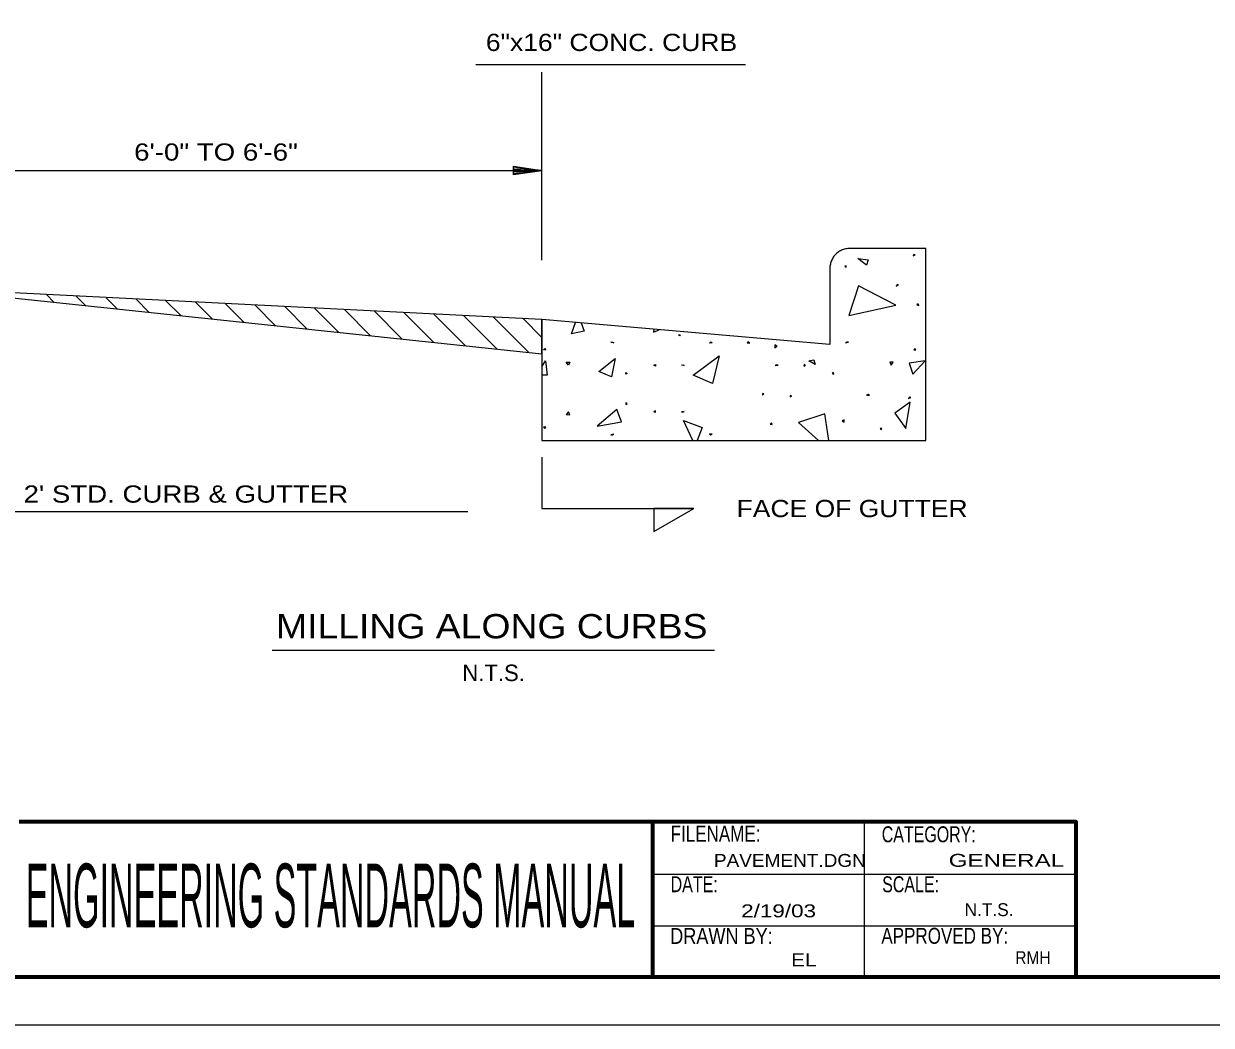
# Model space of a CAD drawing. Extents: x 44.6 to 61.6, y -38.7 to -27.7.
# Drawn here: x 48.86 to 54.61, y -38.7 to -33.85 of the extents above; entities that cross this region are included whole.
import ezdxf
from ezdxf.enums import TextEntityAlignment as Align

# ---------------------------------------------------------------- set-up
doc = ezdxf.new("R2010")
doc.units = 0
doc.header["$LTSCALE"] = 0.025
doc.layers.add('10', color=7, linetype='Continuous')
doc.layers.add('62', color=7, linetype='Continuous')
for name, color, linetype, lineweight in [('6', 7, 'Continuous', 13), ('60', 7, 'Continuous', 13), ('8', 7, 'Continuous', 13), ('9', 7, 'Continuous', 13)]:
    doc.layers.add(name, color=color, linetype=linetype, lineweight=lineweight)

msp = doc.modelspace()

# ---------------------------------------------------------------- linework, layer by layer
at = {"layer": '6'}
for p, q in [((51.05193, -34.05083), (52.35566, -34.05083)), ((51.37066, -34.99727), (51.37066, -34.0885)), ((48.36457, -34.56369), (51.37066, -34.56369)), ((48.97334, -35.1636), (49.01116, -35.20142)), ((49.16368, -35.21779), (49.11703, -35.17117)), ((49.26199, -35.17873), (49.31745, -35.23419)), ((49.46995, -35.25056), (49.40568, -35.18502)), ((49.54936, -35.19258), (49.62372, -35.26569)), ((49.77624, -35.28208), (49.6943, -35.20015)), ((49.83799, -35.20771), (49.93001, -35.29846)), ((50.08251, -35.31485), (49.98168, -35.21402)), ((50.12664, -35.22158), (50.23503, -35.33123)), ((50.3888, -35.34763), (50.27032, -35.22915)), ((50.41526, -35.23671), (50.5413, -35.36275)), ((50.69507, -35.37913), (50.55895, -35.243)), ((50.70264, -35.25056), (50.84759, -35.39552)), ((51.00136, -35.4119), (50.84759, -35.25812)), ((50.99128, -35.26569), (51.15386, -35.42829)), ((51.30764, -35.44467), (51.13497, -35.272)), ((51.27991, -35.27956), (51.37066, -35.37156)), ((51.0127, -36.21479), (48.8158, -36.21479))]:
    msp.add_line(p, q, dxfattribs=at)
at = {"layer": '6', "lineweight": 25}
for points in [[(53.22978, -34.9405), (52.86174, -34.9405), (52.86159, -34.94041), (52.85635, -34.94055), (52.85112, -34.94098), (52.84594, -34.94169), (52.84079, -34.94268), (52.8357, -34.94394), (52.83069, -34.94548), (52.82577, -34.94728), (52.82095, -34.94935), (52.81625, -34.95169), (52.81169, -34.95427), (52.80727, -34.95709), (52.80301, -34.96015), (52.79893, -34.96344), (52.79503, -34.96694), (52.79132, -34.97064), (52.78782, -34.97454), (52.78453, -34.97863), (52.78148, -34.98289), (52.77866, -34.9873), (52.77607, -34.99186), (52.77374, -34.99656), (52.77167, -35.00139), (52.76986, -35.0063), (52.76832, -35.01131), (52.76706, -35.0164), (52.76607, -35.02155), (52.76536, -35.02674), (52.76494, -35.03197), (52.76479, -35.03721), (52.76468, -35.03756), (52.76468, -35.4056), (51.37066, -35.2846), (51.37066, -35.86944), (53.22978, -35.86944)], [(51.37066, -35.2846), (48.36457, -35.13335), (51.37066, -35.45098)]]:
    msp.add_lwpolyline(points, close=True, dxfattribs=at)
at = {"layer": '6'}
for points in [[(52.89955, -34.98967), (52.94997, -34.99596), (52.94241, -35.02117)], [(53.17809, -34.97202), (53.17053, -34.9695), (53.16801, -34.97706)], [(52.84409, -35.03252), (52.84409, -35.02496), (52.83653, -35.02621)], [(52.8567, -35.26569), (53.08482, -35.21527), (52.90332, -35.12075)], [(53.09743, -35.11696), (53.08986, -35.11696), (53.08609, -35.12327)], [(53.19574, -35.21654), (53.19197, -35.20898), (53.18566, -35.21275)], [(51.70468, -35.39425), (51.71349, -35.39425), (51.7198, -35.39677)], [(52.03491, -35.364), (52.03616, -35.35644), (52.04247, -35.36148)], [(52.18236, -35.39804), (52.18868, -35.393), (52.19497, -35.39677)], [(52.37774, -35.39804), (52.37143, -35.393), (52.36514, -35.39677)], [(52.85418, -35.39425), (52.84661, -35.39425), (52.8403, -35.39677)], [(51.37949, -35.43081), (51.38453, -35.4245), (51.38957, -35.43081)], [(52.10297, -35.55433), (52.22901, -35.45979), (52.19749, -35.59467)], [(52.49874, -35.42073), (52.51007, -35.41442), (52.49874, -35.40685)], [(53.18061, -35.43081), (53.17557, -35.4245), (53.17053, -35.43081)], [(51.48914, -35.49131), (51.50553, -35.49004), (51.49922, -35.50517)], [(51.6467, -35.53669), (51.72609, -35.47367), (51.70845, -35.5619)], [(51.91264, -35.50517), (51.9202, -35.50265), (51.92147, -35.51021)], [(52.04624, -35.50517), (52.0538, -35.50392), (52.06011, -35.50644)], [(52.51386, -35.50517), (52.5063, -35.50392), (52.49999, -35.50644)], [(52.64747, -35.50517), (52.63991, -35.50265), (52.63864, -35.51021)], [(52.66259, -35.485), (52.68653, -35.47871), (52.69409, -35.50265)], [(53.07097, -35.49131), (53.05457, -35.49004), (53.06089, -35.50517)], [(53.16676, -35.54929), (53.22599, -35.485), (53.14911, -35.49508)], [(51.77651, -35.54802), (51.77778, -35.54046), (51.78407, -35.5455)], [(52.78359, -35.54802), (52.78232, -35.54046), (52.77603, -35.5455)], [(51.77651, -35.68794), (51.77778, -35.6955), (51.78407, -35.69046)], [(52.4458, -35.64381), (52.43824, -35.64256), (52.43949, -35.65012)], [(52.58066, -35.65517), (52.57309, -35.65138), (52.57309, -35.65894)], [(52.95626, -35.65138), (52.94997, -35.6476), (52.94241, -35.65012)], [(53.15416, -35.68415), (53.07978, -35.73708), (53.13272, -35.81146)], [(53.15668, -35.66146), (53.14911, -35.66021), (53.14532, -35.6665)], [(51.48914, -35.74465), (51.50553, -35.74592), (51.49922, -35.73079)], [(51.63914, -35.8001), (51.75634, -35.77869), (51.73366, -35.71944)], [(51.91264, -35.73079), (51.9202, -35.73331), (51.92147, -35.72575)], [(52.04624, -35.73079), (52.0538, -35.73204), (52.06011, -35.72952)], [(51.37949, -35.80515), (51.38453, -35.81146), (51.38957, -35.80515)], [(52.48614, -35.79254), (52.48234, -35.78498), (52.47605, -35.79002)], [(52.83401, -35.78121), (52.83401, -35.76985), (52.82393, -35.7749)], [(51.70468, -35.84171), (51.71349, -35.84171), (51.7198, -35.83919)], [(52.18236, -35.83792), (52.18868, -35.84296), (52.19497, -35.83919)], [(53.01299, -35.81775), (53.01551, -35.81146), (53.00795, -35.81146)], [(52.10674, -36.19885), (51.9124, -36.19885), (51.9124, -36.31033)]]:
    msp.add_lwpolyline(points, close=True, dxfattribs=at)
for points in [[(51.56099, -35.30098), (51.57611, -35.34131), (51.51434, -35.35392), (51.53326, -35.29846)], [(51.91264, -35.33123), (51.91139, -35.34635), (51.93784, -35.33375)], [(51.37066, -35.51273), (51.3883, -35.485), (51.39714, -35.55433), (51.37066, -35.55306)], [(52.75964, -35.86944), (52.74074, -35.74087), (52.61218, -35.78246), (52.71049, -35.86944)], [(52.1017, -35.86944), (52.05632, -35.77237), (52.14707, -35.80642), (52.12314, -35.86944)], [(51.37066, -35.951), (51.37066, -36.19885), (52.10674, -36.19885)]]:
    msp.add_lwpolyline(points, dxfattribs=at)
at = {"layer": '60', "lineweight": 70}
msp.add_line((51.90778, -38.46427), (51.90778, -37.71468), dxfattribs=at)
at = {"layer": '60'}
for p, q in [((52.93233, -38.46449), (52.93233, -37.71468)), ((51.90778, -37.96843), (53.9569, -37.96843)), ((51.90778, -38.21832), (53.9569, -38.21832))]:
    msp.add_line(p, q, dxfattribs=at)
msp.add_lwpolyline([(61.57033, -38.69864), (44.55984, -38.69864), (44.55984, -27.69184), (61.57033, -27.69184)], close=True, dxfattribs=at)
at = {"layer": '60', "lineweight": 70}
msp.add_lwpolyline([(60.8892, -27.90872), (44.82119, -27.90872), (44.82119, -38.46427), (60.8892, -38.46427)], close=True, dxfattribs=at)
msp.add_lwpolyline([(53.95689, -38.46415), (53.95689, -37.71446), (48.84124, -37.71446)], dxfattribs=at)
at = {"layer": '8'}
msp.add_line((50.06503, -36.88328), (52.20611, -36.88328), dxfattribs=at)
at = {"layer": '9'}
for points in [[(51.36997, -34.56458), (51.23328, -34.58422), (51.23328, -34.54172), (51.37044, -34.56409)], [(51.23339, -34.57741), (51.37066, -34.56369), (51.23339, -34.56369), (51.23339, -34.55683), (51.37066, -34.56369), (51.23339, -34.54997), (51.23339, -34.57055), (51.36378, -34.56369)]]:
    msp.add_lwpolyline(points, dxfattribs=at)

# ---------------------------------------------------------------- texts
at = {"layer": '10'}
msp.add_text('N.T.S.', height=0.08, dxfattribs=at).set_placement((50.98582, -37.03381))
at = {"layer": '6'}
for s, width, p in [('6"x16" CONC. CURB', 1.15, (51.09982, -33.98527)), ('6\'-0" TO 6\'-6"', 1.2, (49.39754, -34.51579)), ("2' STD. CURB & GUTTER", 1.2, (48.86243, -36.17042)), ('FACE OF GUTTER', 1.15, (52.31345, -36.24044))]:
    msp.add_text(s, height=0.08333, dxfattribs=dict(at, width=width)).set_placement(p)
at = {"layer": '60'}
for s, width, p in [('FILENAME:', 0.8, (51.99398, -37.81045)), ('CATEGORY:', 0.75, (53.01594, -37.81332)), ('DATE:', 0.75, (51.99418, -38.05492)), ('SCALE:', 0.75, (53.01799, -38.05529)), ('DRAWN BY:', 0.85, (51.99207, -38.30518)), ('APPROVED BY:', 0.8, (53.01395, -38.30448))]:
    msp.add_text(s, height=0.07704, dxfattribs=dict(at, width=width)).set_placement(p)
at = {"layer": '60', "width": 0.4}
msp.add_text('ENGINEERING STANDARDS MANUAL', height=0.3082, dxfattribs=at).set_placement((50.34761, -38.22498), align=Align.CENTER)
at = {"layer": '62'}
for s, width, p in [('PAVEMENT.DGN ', 1.1, (52.96472, -37.93256)), ('      GENERAL', 1.4, (53.89884, -37.93206))]:
    msp.add_text(s, height=0.0625, dxfattribs=dict(at, width=width)).set_placement(p, align=Align.RIGHT)
for s, width, p in [('2/19/03 ', 1.3, (52.33539, -38.17654)), ('EL ', 1.2, (52.57753, -38.41335)), ('RMH', 0.9, (53.66195, -38.40294))]:
    msp.add_text(s, height=0.0625, dxfattribs=dict(at, width=width)).set_placement(p)
msp.add_text('N.T.S.', height=0.0625, dxfattribs=at).set_placement((53.41679, -38.17077))
at = {"layer": '8', "width": 1.15}
msp.add_text('MILLING ALONG CURBS', height=0.1175, dxfattribs=at).set_placement((50.08406, -36.8268))

doc.saveas('drawing.dxf')
